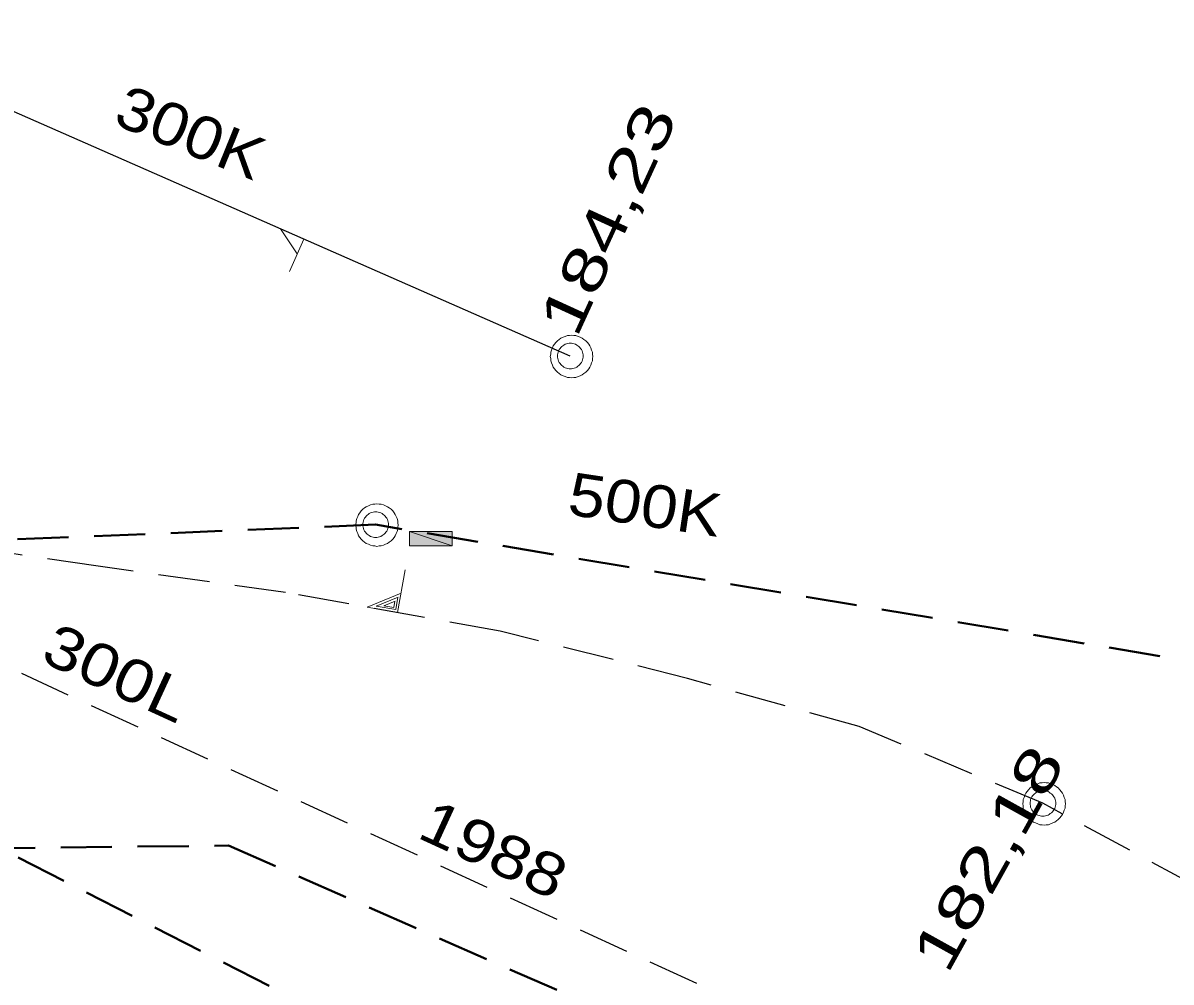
# Model space of a CAD drawing. Extents: x -740851 to -738888, y -1041382 to -1040235.
# Drawn here: x -739788.69 to -739761.8, y -1040513.53 to -1040491.06 of the extents above; entities that cross this region are included whole.
import ezdxf

# ---------------------------------------------------------------- set-up
doc = ezdxf.new("R2010")
doc.units = 0
doc.header["$LTSCALE"] = 0.4
doc.linetypes.add('MEDIUM_DASHED', pattern=[4.5, 3, -1.5])
for name, color, linetype, lineweight in [('18', 7, 'Continuous', 13), ('20', 7, 'MEDIUM_DASHED', 25), ('8', 7, 'Continuous', 13)]:
    doc.layers.add(name, color=color, linetype=linetype, lineweight=lineweight)

msp = doc.modelspace()

# ---------------------------------------------------------------- hatches: boundary and pattern name
at = {"layer": '18'}
msp.add_hatch(color=256, dxfattribs=at).paths.add_polyline_path([(-739779.64, -1040502.97), (-739779.64, -1040503.31), (-739778.64, -1040503.31), (-739778.64, -1040502.97)])

# ---------------------------------------------------------------- linework, layer by layer
at = {"layer": '18', "lineweight": 25}
msp.add_line((-739775.87, -1040498.86), (-739795.67, -1040490.17), dxfattribs=at)
at = {"layer": '18'}
msp.add_line((-739779.64, -1040502.97), (-739778.64, -1040503.31), dxfattribs=at)
at = {"layer": '18', "linetype": 'MEDIUM_DASHED', "lineweight": 40}
msp.add_line((-739746.06, -1040532.45), (-739799.87, -1040504.96), dxfattribs=at)
at = {"layer": '18', "linetype": 'MEDIUM_DASHED', "lineweight": 25}
msp.add_line((-739721.586, -1040532.672), (-739764.8, -1040509.34), dxfattribs=at)
at = {"layer": '18'}
for points in [[(-739782.45, -1040496.88), (-739782.116, -1040496.119), (-739782.659, -1040495.88), (-739782.267, -1040496.462)], [(-739779.738, -1040503.87), (-739779.917, -1040504.87), (-739780.631, -1040504.743), (-739779.836, -1040504.419)], [(-739779.907, -1040504.51), (-739779.959, -1040504.801), (-739780.415, -1040504.72), (-739779.902, -1040504.511)], [(-739779.978, -1040504.606), (-739780.004, -1040504.751), (-739780.238, -1040504.709), (-739779.973, -1040504.607)]]:
    msp.add_lwpolyline(points, dxfattribs=at)
for points in [[(-739775.34, -1040498.87), (-739775.35, -1040498.82), (-739775.35, -1040498.77), (-739775.37, -1040498.72), (-739775.39, -1040498.67), (-739775.41, -1040498.62), (-739775.44, -1040498.58), (-739775.47, -1040498.54), (-739775.51, -1040498.5), (-739775.55, -1040498.47), (-739775.59, -1040498.44), (-739775.64, -1040498.42), (-739775.69, -1040498.4), (-739775.74, -1040498.38), (-739775.79, -1040498.38), (-739775.84, -1040498.37), (-739775.89, -1040498.38), (-739775.94, -1040498.38), (-739775.99, -1040498.4), (-739776.04, -1040498.42), (-739776.09, -1040498.44), (-739776.13, -1040498.47), (-739776.17, -1040498.5), (-739776.21, -1040498.54), (-739776.24, -1040498.58), (-739776.27, -1040498.62), (-739776.29, -1040498.67), (-739776.31, -1040498.72), (-739776.33, -1040498.77), (-739776.33, -1040498.82), (-739776.34, -1040498.87), (-739776.33, -1040498.92), (-739776.33, -1040498.97), (-739776.31, -1040499.02), (-739776.29, -1040499.07), (-739776.27, -1040499.12), (-739776.24, -1040499.16), (-739776.21, -1040499.2), (-739776.17, -1040499.24), (-739776.13, -1040499.27), (-739776.09, -1040499.3), (-739776.04, -1040499.32), (-739775.99, -1040499.34), (-739775.94, -1040499.36), (-739775.89, -1040499.36), (-739775.84, -1040499.37), (-739775.79, -1040499.36), (-739775.74, -1040499.36), (-739775.69, -1040499.34), (-739775.64, -1040499.32), (-739775.59, -1040499.3), (-739775.55, -1040499.27), (-739775.51, -1040499.24), (-739775.47, -1040499.2), (-739775.44, -1040499.16), (-739775.41, -1040499.12), (-739775.39, -1040499.07), (-739775.37, -1040499.02), (-739775.35, -1040498.97), (-739775.35, -1040498.92)], [(-739775.57, -1040498.86), (-739775.57, -1040498.83), (-739775.576, -1040498.8), (-739775.582, -1040498.77), (-739775.594, -1040498.74), (-739775.612, -1040498.71), (-739775.63, -1040498.686), (-739775.648, -1040498.662), (-739775.672, -1040498.638), (-739775.696, -1040498.62), (-739775.72, -1040498.602), (-739775.75, -1040498.584), (-739775.78, -1040498.572), (-739775.81, -1040498.566), (-739775.84, -1040498.56), (-739775.87, -1040498.56), (-739775.9, -1040498.56), (-739775.93, -1040498.566), (-739775.96, -1040498.572), (-739775.99, -1040498.584), (-739776.02, -1040498.602), (-739776.044, -1040498.62), (-739776.068, -1040498.638), (-739776.092, -1040498.662), (-739776.11, -1040498.686), (-739776.128, -1040498.71), (-739776.146, -1040498.74), (-739776.158, -1040498.77), (-739776.164, -1040498.8), (-739776.17, -1040498.83), (-739776.17, -1040498.86), (-739776.17, -1040498.89), (-739776.164, -1040498.92), (-739776.158, -1040498.95), (-739776.146, -1040498.98), (-739776.128, -1040499.01), (-739776.11, -1040499.034), (-739776.092, -1040499.058), (-739776.068, -1040499.082), (-739776.044, -1040499.1), (-739776.02, -1040499.118), (-739775.99, -1040499.136), (-739775.96, -1040499.148), (-739775.93, -1040499.154), (-739775.9, -1040499.16), (-739775.87, -1040499.16), (-739775.84, -1040499.16), (-739775.81, -1040499.154), (-739775.78, -1040499.148), (-739775.75, -1040499.136), (-739775.72, -1040499.118), (-739775.696, -1040499.1), (-739775.672, -1040499.082), (-739775.648, -1040499.058), (-739775.63, -1040499.034), (-739775.612, -1040499.01), (-739775.594, -1040498.98), (-739775.582, -1040498.95), (-739775.576, -1040498.92), (-739775.57, -1040498.89)], [(-739779.9, -1040502.82), (-739779.91, -1040502.77), (-739779.91, -1040502.72), (-739779.93, -1040502.67), (-739779.95, -1040502.62), (-739779.97, -1040502.57), (-739780, -1040502.53), (-739780.03, -1040502.49), (-739780.07, -1040502.45), (-739780.11, -1040502.42), (-739780.15, -1040502.39), (-739780.2, -1040502.37), (-739780.25, -1040502.35), (-739780.3, -1040502.33), (-739780.35, -1040502.33), (-739780.4, -1040502.32), (-739780.45, -1040502.33), (-739780.5, -1040502.33), (-739780.55, -1040502.35), (-739780.6, -1040502.37), (-739780.65, -1040502.39), (-739780.69, -1040502.42), (-739780.73, -1040502.45), (-739780.77, -1040502.49), (-739780.8, -1040502.53), (-739780.83, -1040502.57), (-739780.85, -1040502.62), (-739780.87, -1040502.67), (-739780.89, -1040502.72), (-739780.89, -1040502.77), (-739780.9, -1040502.82), (-739780.89, -1040502.87), (-739780.89, -1040502.92), (-739780.87, -1040502.97), (-739780.85, -1040503.02), (-739780.83, -1040503.07), (-739780.8, -1040503.11), (-739780.77, -1040503.15), (-739780.73, -1040503.19), (-739780.69, -1040503.22), (-739780.65, -1040503.25), (-739780.6, -1040503.27), (-739780.55, -1040503.29), (-739780.5, -1040503.31), (-739780.45, -1040503.31), (-739780.4, -1040503.32), (-739780.35, -1040503.31), (-739780.3, -1040503.31), (-739780.25, -1040503.29), (-739780.2, -1040503.27), (-739780.15, -1040503.25), (-739780.11, -1040503.22), (-739780.07, -1040503.19), (-739780.03, -1040503.15), (-739780, -1040503.11), (-739779.97, -1040503.07), (-739779.95, -1040503.02), (-739779.93, -1040502.97), (-739779.91, -1040502.92), (-739779.91, -1040502.87)], [(-739780.13, -1040502.81), (-739780.13, -1040502.78), (-739780.136, -1040502.75), (-739780.142, -1040502.72), (-739780.154, -1040502.69), (-739780.172, -1040502.66), (-739780.19, -1040502.636), (-739780.208, -1040502.612), (-739780.232, -1040502.588), (-739780.256, -1040502.57), (-739780.28, -1040502.552), (-739780.31, -1040502.534), (-739780.34, -1040502.522), (-739780.37, -1040502.516), (-739780.4, -1040502.51), (-739780.43, -1040502.51), (-739780.46, -1040502.51), (-739780.49, -1040502.516), (-739780.52, -1040502.522), (-739780.55, -1040502.534), (-739780.58, -1040502.552), (-739780.604, -1040502.57), (-739780.628, -1040502.588), (-739780.652, -1040502.612), (-739780.67, -1040502.636), (-739780.688, -1040502.66), (-739780.706, -1040502.69), (-739780.718, -1040502.72), (-739780.724, -1040502.75), (-739780.73, -1040502.78), (-739780.73, -1040502.81), (-739780.73, -1040502.84), (-739780.724, -1040502.87), (-739780.718, -1040502.9), (-739780.706, -1040502.93), (-739780.688, -1040502.96), (-739780.67, -1040502.984), (-739780.652, -1040503.008), (-739780.628, -1040503.032), (-739780.604, -1040503.05), (-739780.58, -1040503.068), (-739780.55, -1040503.086), (-739780.52, -1040503.098), (-739780.49, -1040503.104), (-739780.46, -1040503.11), (-739780.43, -1040503.11), (-739780.4, -1040503.11), (-739780.37, -1040503.104), (-739780.34, -1040503.098), (-739780.31, -1040503.086), (-739780.28, -1040503.068), (-739780.256, -1040503.05), (-739780.232, -1040503.032), (-739780.208, -1040503.008), (-739780.19, -1040502.984), (-739780.172, -1040502.96), (-739780.154, -1040502.93), (-739780.142, -1040502.9), (-739780.136, -1040502.87), (-739780.13, -1040502.84)], [(-739779.64, -1040502.97), (-739779.64, -1040503.31), (-739778.64, -1040503.31), (-739778.64, -1040502.97)], [(-739764.27, -1040509.35), (-739764.28, -1040509.3), (-739764.28, -1040509.25), (-739764.3, -1040509.2), (-739764.32, -1040509.15), (-739764.34, -1040509.1), (-739764.37, -1040509.06), (-739764.4, -1040509.02), (-739764.44, -1040508.98), (-739764.48, -1040508.95), (-739764.52, -1040508.92), (-739764.57, -1040508.9), (-739764.62, -1040508.88), (-739764.67, -1040508.86), (-739764.72, -1040508.86), (-739764.77, -1040508.85), (-739764.82, -1040508.86), (-739764.87, -1040508.86), (-739764.92, -1040508.88), (-739764.97, -1040508.9), (-739765.02, -1040508.92), (-739765.06, -1040508.95), (-739765.1, -1040508.98), (-739765.14, -1040509.02), (-739765.17, -1040509.06), (-739765.2, -1040509.1), (-739765.22, -1040509.15), (-739765.24, -1040509.2), (-739765.26, -1040509.25), (-739765.26, -1040509.3), (-739765.27, -1040509.35), (-739765.26, -1040509.4), (-739765.26, -1040509.45), (-739765.24, -1040509.5), (-739765.22, -1040509.55), (-739765.2, -1040509.6), (-739765.17, -1040509.64), (-739765.14, -1040509.68), (-739765.1, -1040509.72), (-739765.06, -1040509.75), (-739765.02, -1040509.78), (-739764.97, -1040509.8), (-739764.92, -1040509.82), (-739764.87, -1040509.84), (-739764.82, -1040509.84), (-739764.77, -1040509.85), (-739764.72, -1040509.84), (-739764.67, -1040509.84), (-739764.62, -1040509.82), (-739764.57, -1040509.8), (-739764.52, -1040509.78), (-739764.48, -1040509.75), (-739764.44, -1040509.72), (-739764.4, -1040509.68), (-739764.37, -1040509.64), (-739764.34, -1040509.6), (-739764.32, -1040509.55), (-739764.3, -1040509.5), (-739764.28, -1040509.45), (-739764.28, -1040509.4)], [(-739764.5, -1040509.34), (-739764.5, -1040509.31), (-739764.506, -1040509.28), (-739764.512, -1040509.25), (-739764.524, -1040509.22), (-739764.542, -1040509.19), (-739764.56, -1040509.166), (-739764.578, -1040509.142), (-739764.602, -1040509.118), (-739764.626, -1040509.1), (-739764.65, -1040509.082), (-739764.68, -1040509.064), (-739764.71, -1040509.052), (-739764.74, -1040509.046), (-739764.77, -1040509.04), (-739764.8, -1040509.04), (-739764.83, -1040509.04), (-739764.86, -1040509.046), (-739764.89, -1040509.052), (-739764.92, -1040509.064), (-739764.95, -1040509.082), (-739764.974, -1040509.1), (-739764.998, -1040509.118), (-739765.022, -1040509.142), (-739765.04, -1040509.166), (-739765.058, -1040509.19), (-739765.076, -1040509.22), (-739765.088, -1040509.25), (-739765.094, -1040509.28), (-739765.1, -1040509.31), (-739765.1, -1040509.34), (-739765.1, -1040509.37), (-739765.094, -1040509.4), (-739765.088, -1040509.43), (-739765.076, -1040509.46), (-739765.058, -1040509.49), (-739765.04, -1040509.514), (-739765.022, -1040509.538), (-739764.998, -1040509.562), (-739764.974, -1040509.58), (-739764.95, -1040509.598), (-739764.92, -1040509.616), (-739764.89, -1040509.628), (-739764.86, -1040509.634), (-739764.83, -1040509.64), (-739764.8, -1040509.64), (-739764.77, -1040509.64), (-739764.74, -1040509.634), (-739764.71, -1040509.628), (-739764.68, -1040509.616), (-739764.65, -1040509.598), (-739764.626, -1040509.58), (-739764.602, -1040509.562), (-739764.578, -1040509.538), (-739764.56, -1040509.514), (-739764.542, -1040509.49), (-739764.524, -1040509.46), (-739764.512, -1040509.43), (-739764.506, -1040509.4), (-739764.5, -1040509.37)]]:
    msp.add_lwpolyline(points, close=True, dxfattribs=at)
at = {"layer": '18', "linetype": 'MEDIUM_DASHED', "lineweight": 25}
msp.add_lwpolyline([(-739764.8, -1040509.34), (-739769.103, -1040507.543), (-739773.123, -1040506.414), (-739777.515, -1040505.303), (-739782.543, -1040504.403), (-739786.933, -1040503.786), (-739791.776, -1040503.067), (-739793.941, -1040502.746), (-739796.322, -1040502.462), (-739800.245, -1040502.273), (-739807.808, -1040502.015), (-739813.37, -1040501.84)], dxfattribs=at)
at = {"layer": '20', "lineweight": 40}
for p, q in [((-739780.43, -1040502.81), (-739795.29, -1040503.42)), ((-739747.86, -1040508.27), (-739780.43, -1040502.81))]:
    msp.add_line(p, q, dxfattribs=at)
at = {"layer": '8', "linetype": 'MEDIUM_DASHED', "lineweight": 25}
msp.add_lwpolyline([(-739769.636, -1040515.065), (-739798.96, -1040501.6), (-739806.89, -1040499.33), (-739808.75, -1040483.96), (-739809.48, -1040483.712)], dxfattribs=at)
at = {"layer": '8', "linetype": 'MEDIUM_DASHED', "lineweight": 40}
msp.add_lwpolyline([(-739800.406, -1040510.509), (-739783.874, -1040510.33), (-739769.682, -1040516.575), (-739747.937, -1040528.604), (-739744.345, -1040531.012), (-739722.292, -1040550.654), (-739710.435, -1040562.012), (-739703.68, -1040568.1)], dxfattribs=at)

# ---------------------------------------------------------------- texts
at = {"layer": '18'}
for s, rotation, width, p in [('300K', 337.981, 1.15, (-739786.617, -1040493.409)), ('184,23', 65.411, 1.4, (-739775.726, -1040498.465)), ('500K', 351.483, 1.15, (-739775.968, -1040502.567)), ('182,18', 60.936, 1.4, (-739767.038, -1040513.371))]:
    msp.add_text(s, height=1, rotation=rotation, dxfattribs=dict(at, width=width)).set_placement(p)
at = {"layer": '8', "width": 1.2}
for s, p in [('300L', (-739788.317, -1040505.995)), ('1988', (-739779.495, -1040510.127))]:
    msp.add_text(s, height=1, rotation=335.336, dxfattribs=at).set_placement(p)

doc.saveas('drawing.dxf')
